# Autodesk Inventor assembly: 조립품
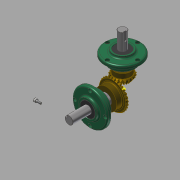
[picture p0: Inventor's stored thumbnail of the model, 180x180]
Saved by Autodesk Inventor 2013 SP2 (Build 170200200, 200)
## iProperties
Created: 2023-01
Part Number: 조립품
Document SubType Name: Assembly
Designer: aa
Author: aa
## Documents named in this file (14)
- C:\Users\aa\Desktop\730106V1028\730106V1028\조립품.iam
- C:\Users\aa\Desktop\730106V1025\본체.ipt
- C:\Users\aa\Desktop\730106V1025\서브 베벨기어.ipt
- C:\Users\aa\Desktop\730106V1025\오일실 17 32 8.ipt
- C:\Users\aa\Desktop\730106V1025\커버.ipt
- C:\Users\aa\Desktop\730106V1025\메인 베벨기어.ipt
- C:\Users\aa\Desktop\730106V1025\베어링 6203.ipt
- C:\Users\aa\Desktop\730106V1025\M4.ipt
- C:\Users\aa\Desktop\730106V1025\서브 축.ipt
- 서브 축.ipt
- C:\Users\aa\Desktop\730106V1025\메인 축.ipt
- 메인 축.ipt
- C:\Users\aa\Desktop\730106V1025\키 4x4.ipt
- C:\Users\aa\Desktop\730106V1025\키 5x5.ipt
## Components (1 placed, 1 different names)
1. M4:1
